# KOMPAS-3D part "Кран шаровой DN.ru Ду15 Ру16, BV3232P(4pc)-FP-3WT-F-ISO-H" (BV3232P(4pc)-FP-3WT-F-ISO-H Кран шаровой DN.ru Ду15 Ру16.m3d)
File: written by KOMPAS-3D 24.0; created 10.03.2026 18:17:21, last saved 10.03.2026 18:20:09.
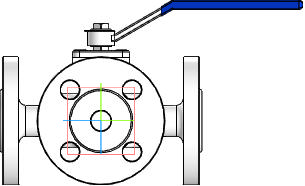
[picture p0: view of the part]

Document properties: Автор: R2D2; Полное имя файла: E:\Работа\Зайцев\BV3232P(4pc)-FP-3WT-F-ISO-H Кран шаровой DN.ru Ду15-100 Ру16\DN15\BV3232P(4pc)-FP-3WT-F-ISO-H Кран шаровой DN.ru Ду15 Ру16.m3d

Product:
- Part/product: Кран шаровой DN.ru Ду15 Ру16  | designation BV3232P(4pc)-FP-3WT-F-ISO-H
    Масса: 3.5
    Раздел спецификации: Прочие изделия
    Примечание: D160-36346

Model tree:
1. Операция без истории:1

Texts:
  BV3232P(4pc)-FP-3WT-F-ISO-H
